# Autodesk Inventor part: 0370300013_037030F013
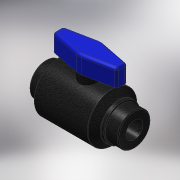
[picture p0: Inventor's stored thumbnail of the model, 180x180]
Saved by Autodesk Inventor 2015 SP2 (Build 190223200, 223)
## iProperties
Created: 2017-06
Part Number: 0370300013_037030F013
Material: PVC-Piping
Description: PLASSON BALL VALVE DN32 FEMALE 1.1/4" BSPT
Document SubType Name: Modeling
Designer: KIM
Mass: 634.249 g
Surface Area: 497.046 cm^2
Volume: 453.035 cm^3
Density: 1.4 g/cm^3
Appearance: Black Cast
Author: KIM
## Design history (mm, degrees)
derived "03703.ipt"
feature "Solid1::03703.ipt"
tag "TaggingFeature1"
body "Solid1"
other parameters: "d0" = 118, "d3" = 72, "d5" = 38.952, "d6" = 38.952, "d8" = 55, "d9" = 16, "d10" = 60.5, "d11" = 15.0485, "d12" = 135 deg, "d14" = 1.9476, "d24" = 23.3712, "d25" = 46.8, "d27" = 23.3712, "d28" = 11.6856, "d29" = 23.2, "d30" = 0, "d32" = 51.41664, "d33" = 5.8428, "d34" = 1.9476, "Rc_" = 38.952, "A_1" = 36, "H_" = 118, "B_" = 55, "E_" = 1, "d31" = 46.7424
